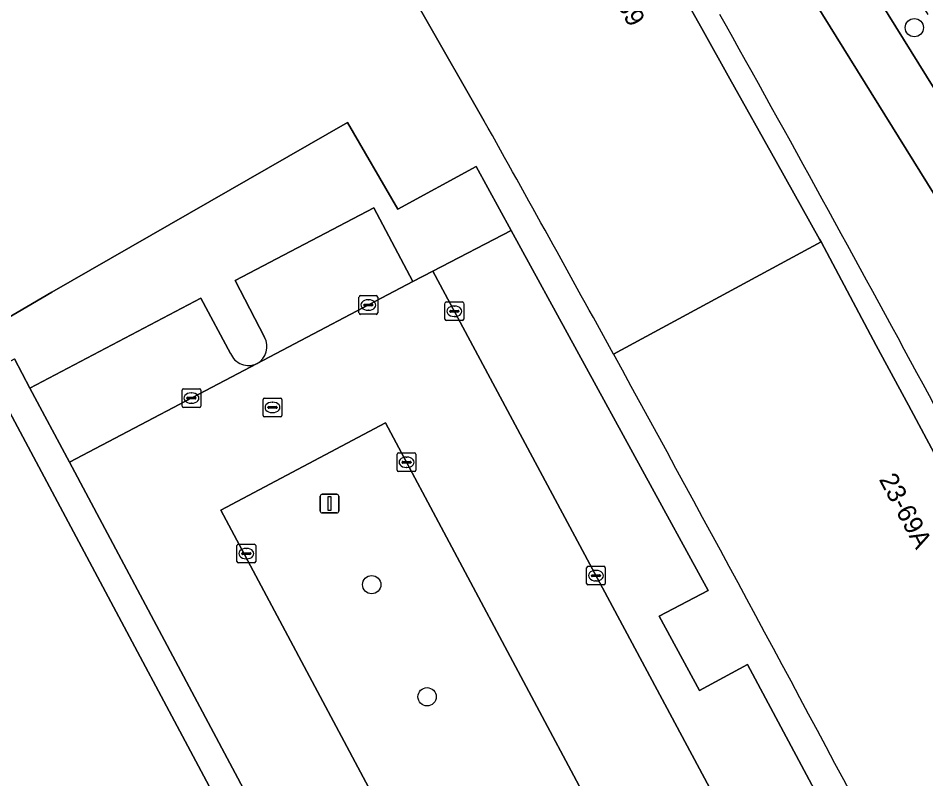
# Model space of a CAD drawing. Extents: x 160304 to 160955, y 383684 to 384161.
# Drawn here: x 160780.6 to 160829.2, y 383959.05 to 383999.81 of the extents above; entities that cross this region are included whole.
import ezdxf

# ---------------------------------------------------------------- set-up
doc = ezdxf.new("R2010")
doc.units = 0
for name, color, linetype in [('IMGEO_Boom', 7, 'Continuous'), ('IMGEO_Erf', 7, 'Continuous'), ('IMGEO_Fietspad_open', 7, 'Continuous'), ('IMGEO_Groenvoorziening', 7, 'Continuous'), ('IMGEO_Haag', 7, 'Continuous'), ('IMGEO_Kolk', 7, 'Continuous'), ('IMGEO_Lichtmast', 7, 'Continuous'), ('IMGEO_Pand', 7, 'Continuous'), ('IMGEO_Pand_nummerreeks', 7, 'Continuous'), ('IMGEO_Parkeervlak_open', 7, 'Continuous'), ('IMGEO_Rijbaan_lokaal_open', 7, 'Continuous'), ('IMGEO_Rioolput', 7, 'Continuous'), ('IMGEO_Voetpad_open', 7, 'Continuous')]:
    doc.layers.add(name, color=color, linetype=linetype)

msp = doc.modelspace()

# ---------------------------------------------------------------- linework, layer by layer
at = {"layer": 'IMGEO_Boom'}
for centre in [(160828.586, 383999.297), (160799.535, 383969.454), (160802.499, 383963.445)]:
    msp.add_circle(centre, 0.489, dxfattribs=at)
at = {"layer": 'IMGEO_Erf'}
for points in [[(160805.557, 383994.294), (160802.29, 384000), (160797.022, 384009.201)], [(160812.69, 384007.286), (160817.202, 383999.253), (160818.714, 383996.546), (160821.191, 383992.119), (160823.516, 383987.966), (160823.591, 383987.825), (160826.547, 383982.272), (160828.272, 383979.078), (160832.639, 383970.896), (160838.66, 383959.615), (160839.632, 383960.211)], [(160779.201, 383983.25), (160782.415, 383985.126), (160798.232, 383994.207), (160800.93, 383989.567), (160805.122, 383991.849), (160806.997, 383988.421), (160817.543, 383969.142), (160814.927, 383967.761), (160817.081, 383963.773), (160819.647, 383965.18), (160824.324, 383956.417), (160820.023, 383954.079), (160822.082, 383950.245), (160822.177, 383950.069), (160822.338, 383950.156), (160822.731, 383950.367), (160823.414, 383949.093), (160823.931, 383948.129), (160828.069, 383940.418), (160824.093, 383938.301)], [(160773.144, 383991.809), (160792.547, 383955.437), (160789.439, 383953.779), (160789.901, 383952.915), (160792.759, 383954.5), (160793.228, 383953.573), (160794.841, 383954.422), (160783.352, 383976.011), (160781.236, 383979.986), (160780.405, 383981.548)]]:
    msp.add_lwpolyline(points, dxfattribs=at)
for centre, radius, start, end in [((159525.369, 383277.181), 1481.154, 27.461144, 29.2099), ((159123.204, 383053.921), 1927.333, 28.779303, 29.203562), ((159143.463, 383065.194), 1904.149, 27.815062, 28.775508)]:
    msp.add_arc(centre, radius, start, end, dxfattribs=at)
at = {"layer": 'IMGEO_Fietspad_open'}
for points in [[(160751.873, 384115.337), (160755.715, 384109.34), (160755.728, 384109.32), (160788.518, 384056.578), (160823.662, 384000), (160830.017, 383989.77), (160839.554, 383974.387)], [(160842.328, 383975.591), (160832.842, 383990.888), (160827.177, 384000), (160814.975, 384019.629), (160813.456, 384022.072), (160805.259, 384035.309), (160768.526, 384094.486), (160764.835, 384100.432), (160758.942, 384109.926), (160757.079, 384112.871)]]:
    msp.add_lwpolyline(points, dxfattribs=at)
at = {"layer": 'IMGEO_Groenvoorziening'}
msp.add_lwpolyline([(160829.327, 384000), (160823.073, 384010.065), (160816.551, 384020.604), (160814.975, 384019.629), (160827.177, 384000), (160832.842, 383990.888), (160842.328, 383975.591)], dxfattribs=at)
at = {"layer": 'IMGEO_Haag'}
msp.add_lwpolyline([(160829.327, 384000), (160823.073, 384010.065), (160816.551, 384020.604), (160814.975, 384019.629), (160827.177, 384000), (160832.842, 383990.888), (160842.328, 383975.591)], dxfattribs=at)
at = {"layer": 'IMGEO_Kolk'}
for p, q in [((160798.852, 383984.011), (160798.852, 383984.863)), ((160798.927, 383984.937), (160799.779, 383984.937)), ((160799.853, 383984.863), (160799.853, 383984.011)), ((160799.111, 383984.431), (160799.111, 383984.443)), ((160799.549, 383984.394), (160799.151, 383984.394)), ((160799.154, 383984.48), (160799.552, 383984.48)), ((160799.34, 383984.717), (160799.365, 383984.717)), ((160799.595, 383984.443), (160799.595, 383984.431)), ((160803.456, 383983.674), (160803.456, 383984.526)), ((160803.531, 383984.6), (160804.383, 383984.6)), ((160803.944, 383984.38), (160803.969, 383984.38)), ((160804.457, 383984.526), (160804.457, 383983.674)), ((160799.779, 383983.937), (160798.927, 383983.937)), ((160799.363, 383984.157), (160799.338, 383984.157)), ((160803.715, 383984.094), (160803.715, 383984.106)), ((160804.153, 383984.057), (160803.755, 383984.057)), ((160803.758, 383984.143), (160804.156, 383984.143)), ((160804.199, 383984.106), (160804.199, 383984.094)), ((160804.383, 383983.6), (160803.531, 383983.6)), ((160803.967, 383983.82), (160803.942, 383983.82)), ((160789.38, 383979.024), (160789.38, 383979.876)), ((160789.455, 383979.95), (160790.307, 383979.95)), ((160789.868, 383979.73), (160789.893, 383979.73)), ((160790.381, 383979.876), (160790.381, 383979.024)), ((160789.639, 383979.444), (160789.639, 383979.456)), ((160790.077, 383979.407), (160789.679, 383979.407)), ((160789.682, 383979.493), (160790.08, 383979.493)), ((160789.891, 383979.17), (160789.866, 383979.17)), ((160790.123, 383979.456), (160790.123, 383979.444)), ((160790.307, 383978.95), (160789.455, 383978.95)), ((160800.897, 383975.584), (160800.897, 383976.436)), ((160800.972, 383976.51), (160801.824, 383976.51)), ((160801.385, 383976.29), (160801.41, 383976.29)), ((160801.898, 383976.436), (160801.898, 383975.584)), ((160801.156, 383976.004), (160801.156, 383976.016)), ((160801.594, 383975.967), (160801.196, 383975.967)), ((160801.199, 383976.053), (160801.597, 383976.053)), ((160801.408, 383975.73), (160801.383, 383975.73)), ((160801.64, 383976.016), (160801.64, 383976.004)), ((160801.824, 383975.51), (160800.972, 383975.51)), ((160792.32, 383970.69), (160792.32, 383971.542)), ((160792.395, 383971.616), (160793.247, 383971.616)), ((160792.808, 383971.396), (160792.833, 383971.396)), ((160793.321, 383971.542), (160793.321, 383970.69)), ((160792.579, 383971.11), (160792.579, 383971.122)), ((160793.017, 383971.073), (160792.619, 383971.073)), ((160792.622, 383971.159), (160793.02, 383971.159)), ((160792.831, 383970.836), (160792.806, 383970.836)), ((160793.063, 383971.122), (160793.063, 383971.11)), ((160793.247, 383970.616), (160792.395, 383970.616)), ((160811.037, 383969.51), (160811.037, 383970.362)), ((160811.112, 383970.436), (160811.964, 383970.436)), ((160812.038, 383970.362), (160812.038, 383969.51)), ((160811.296, 383969.93), (160811.296, 383969.942)), ((160811.734, 383969.893), (160811.336, 383969.893)), ((160811.339, 383969.979), (160811.737, 383969.979)), ((160811.525, 383970.216), (160811.55, 383970.216)), ((160811.78, 383969.942), (160811.78, 383969.93)), ((160811.964, 383969.436), (160811.112, 383969.436)), ((160811.548, 383969.656), (160811.523, 383969.656))]:
    msp.add_line(p, q, dxfattribs=at)
for points in [[(160798.852, 383984.011), (160798.852, 383984.863)], [(160798.927, 383984.937), (160799.779, 383984.937)], [(160799.853, 383984.863), (160799.853, 383984.011)], [(160803.456, 383983.674), (160803.456, 383984.526)], [(160803.531, 383984.6), (160804.383, 383984.6)], [(160804.457, 383984.526), (160804.457, 383983.674)], [(160799.779, 383983.937), (160798.927, 383983.937)], [(160804.383, 383983.6), (160803.531, 383983.6)], [(160789.38, 383979.024), (160789.38, 383979.876)], [(160789.455, 383979.95), (160790.307, 383979.95)], [(160790.381, 383979.876), (160790.381, 383979.024)], [(160790.307, 383978.95), (160789.455, 383978.95)], [(160800.897, 383975.584), (160800.897, 383976.436)], [(160800.972, 383976.51), (160801.824, 383976.51)], [(160801.898, 383976.436), (160801.898, 383975.584)], [(160801.824, 383975.51), (160800.972, 383975.51)], [(160792.32, 383970.69), (160792.32, 383971.542)], [(160792.395, 383971.616), (160793.247, 383971.616)], [(160793.321, 383971.542), (160793.321, 383970.69)], [(160793.247, 383970.616), (160792.395, 383970.616)], [(160811.037, 383969.51), (160811.037, 383970.362)], [(160811.112, 383970.436), (160811.964, 383970.436)], [(160812.038, 383970.362), (160812.038, 383969.51)], [(160811.964, 383969.436), (160811.112, 383969.436)]]:
    msp.add_lwpolyline(points, dxfattribs=at)
for centre, radius, start, end in [((160798.929, 383984.861), 0.0765, 91.552, 178.448), ((160798.929, 383984.861), 0.0765, 91.552, 178.448), ((160799.777, 383984.861), 0.0765, 1.552, 88.448), ((160799.777, 383984.861), 0.0765, 1.552, 88.448), ((160799.151, 383984.44), 0.0403, 85.8775, 175.7526), ((160799.148, 383984.43), 0.0366, 178.938, 274.7102), ((160799.552, 383984.437), 0.043, 264.8664, 352.4533), ((160799.556, 383984.442), 0.0386, 1.7309, 96.639), ((160803.533, 383984.524), 0.0765, 91.552, 178.448), ((160803.533, 383984.524), 0.0765, 91.552, 178.448), ((160804.381, 383984.524), 0.0765, 1.552, 88.448), ((160804.381, 383984.524), 0.0765, 1.552, 88.448), ((160798.929, 383984.013), 0.0765, 181.552, 268.448), ((160798.929, 383984.013), 0.0765, 181.552, 268.448), ((160799.777, 383984.013), 0.0765, 271.552, 358.448), ((160799.777, 383984.013), 0.0765, 271.552, 358.448), ((160803.755, 383984.103), 0.0403, 85.8775, 175.7526), ((160803.752, 383984.093), 0.0366, 178.938, 274.7102), ((160804.156, 383984.1), 0.043, 264.8664, 352.4533), ((160804.16, 383984.105), 0.0386, 1.7309, 96.639), ((160803.533, 383983.676), 0.0765, 181.552, 268.448), ((160803.533, 383983.676), 0.0765, 181.552, 268.448), ((160804.381, 383983.676), 0.0765, 271.552, 358.448), ((160804.381, 383983.676), 0.0765, 271.552, 358.448), ((160789.457, 383979.874), 0.0765, 91.552, 178.448), ((160789.457, 383979.874), 0.0765, 91.552, 178.448), ((160790.305, 383979.874), 0.0765, 1.552, 88.448), ((160790.305, 383979.874), 0.0765, 1.552, 88.448), ((160789.679, 383979.453), 0.0403, 85.8775, 175.7526), ((160789.676, 383979.443), 0.0366, 178.938, 274.7102), ((160790.08, 383979.45), 0.043, 264.8664, 352.4533), ((160790.084, 383979.455), 0.0386, 1.7309, 96.639), ((160789.457, 383979.026), 0.0765, 181.552, 268.448), ((160789.457, 383979.026), 0.0765, 181.552, 268.448), ((160790.305, 383979.026), 0.0765, 271.552, 358.448), ((160790.305, 383979.026), 0.0765, 271.552, 358.448), ((160800.974, 383976.434), 0.0765, 91.552, 178.448), ((160800.974, 383976.434), 0.0765, 91.552, 178.448), ((160801.822, 383976.434), 0.0765, 1.552, 88.448), ((160801.822, 383976.434), 0.0765, 1.552, 88.448), ((160801.196, 383976.013), 0.0403, 85.8775, 175.7526), ((160801.193, 383976.003), 0.0366, 178.938, 274.7102), ((160801.597, 383976.01), 0.043, 264.8664, 352.4533), ((160801.601, 383976.015), 0.0386, 1.7309, 96.639), ((160800.974, 383975.586), 0.0765, 181.552, 268.448), ((160800.974, 383975.586), 0.0765, 181.552, 268.448), ((160801.822, 383975.586), 0.0765, 271.552, 358.448), ((160801.822, 383975.586), 0.0765, 271.552, 358.448), ((160792.397, 383971.54), 0.0765, 91.552, 178.448), ((160792.397, 383971.54), 0.0765, 91.552, 178.448), ((160793.245, 383971.54), 0.0765, 1.552, 88.448), ((160793.245, 383971.54), 0.0765, 1.552, 88.448), ((160792.619, 383971.119), 0.0403, 85.8775, 175.7526), ((160792.616, 383971.109), 0.0366, 178.938, 274.7102), ((160793.02, 383971.116), 0.043, 264.8664, 352.4533), ((160793.024, 383971.121), 0.0386, 1.7309, 96.639), ((160792.397, 383970.692), 0.0765, 181.552, 268.448), ((160792.397, 383970.692), 0.0765, 181.552, 268.448), ((160793.245, 383970.692), 0.0765, 271.552, 358.448), ((160793.245, 383970.692), 0.0765, 271.552, 358.448), ((160811.114, 383970.36), 0.0765, 91.552, 178.448), ((160811.114, 383970.36), 0.0765, 91.552, 178.448), ((160811.962, 383970.36), 0.0765, 1.552, 88.448), ((160811.962, 383970.36), 0.0765, 1.552, 88.448), ((160811.336, 383969.939), 0.0403, 85.8775, 175.7526), ((160811.333, 383969.929), 0.0366, 178.938, 274.7102), ((160811.737, 383969.936), 0.043, 264.8664, 352.4533), ((160811.741, 383969.941), 0.0386, 1.7309, 96.639), ((160811.114, 383969.512), 0.0765, 181.552, 268.448), ((160811.114, 383969.512), 0.0765, 181.552, 268.448), ((160811.962, 383969.512), 0.0765, 271.552, 358.448), ((160811.962, 383969.512), 0.0765, 271.552, 358.448)]:
    msp.add_arc(centre, radius, start, end, dxfattribs=at)
for centre, major_axis, ratio, start_param, end_param in [((160799.339, 383984.437), (-0.387, 0.002), 0.722429, 4.712389, 7.853982), ((160799.364, 383984.437), (-0.39, 0.002), 0.717154, 1.570796, 4.712389), ((160803.943, 383984.1), (-0.387, 0.002), 0.722429, 4.712389, 7.853982), ((160803.968, 383984.1), (-0.39, 0.002), 0.717154, 1.570796, 4.712389), ((160789.867, 383979.45), (-0.387, 0.002), 0.722429, 4.712389, 7.853982), ((160789.892, 383979.45), (-0.39, 0.002), 0.717154, 1.570796, 4.712389), ((160801.384, 383976.01), (-0.387, 0.002), 0.722429, 4.712389, 7.853982), ((160801.409, 383976.01), (-0.39, 0.002), 0.717154, 1.570796, 4.712389), ((160792.807, 383971.116), (-0.387, 0.002), 0.722429, 4.712389, 7.853982), ((160792.832, 383971.116), (-0.39, 0.002), 0.717154, 1.570796, 4.712389), ((160811.524, 383969.936), (-0.387, 0.002), 0.722429, 4.712389, 7.853982), ((160811.549, 383969.936), (-0.39, 0.002), 0.717154, 1.570796, 4.712389)]:
    msp.add_ellipse(centre, major_axis=major_axis, ratio=ratio, start_param=start_param, end_param=end_param, dxfattribs=at)
at = {"layer": 'IMGEO_Lichtmast'}
for p, q in [((160796.781, 383973.394), (160796.781, 383974.194)), ((160796.781, 383974.194), (160796.781, 383973.394)), ((160796.881, 383974.294), (160797.671, 383974.294)), ((160797.671, 383974.294), (160796.881, 383974.294)), ((160797.771, 383974.194), (160797.771, 383973.394)), ((160797.771, 383973.394), (160797.771, 383974.194)), ((160797.671, 383973.294), (160796.881, 383973.294)), ((160796.881, 383973.294), (160797.671, 383973.294))]:
    msp.add_line(p, q, dxfattribs=at)
msp.add_lwpolyline([(160797.201, 383974.169), (160797.351, 383974.169), (160797.351, 383973.419), (160797.201, 383973.419), (160797.201, 383974.169)], dxfattribs=at)
for centre, start, end in [((160796.881, 383974.194), 90, 180), ((160796.881, 383974.194), 90, 180), ((160797.671, 383974.194), 0, 90), ((160797.671, 383974.194), 360, 90), ((160796.881, 383973.394), 180, 270), ((160796.881, 383973.394), 180, 270), ((160797.671, 383973.394), 270, 0), ((160797.671, 383973.394), 270, 0)]:
    msp.add_arc(centre, 0.1, start, end, dxfattribs=at)
at = {"layer": 'IMGEO_Pand'}
for points in [[(160808.064, 384015.523), (160797.022, 384009.201), (160802.29, 384000), (160805.557, 383994.294)], [(160812.474, 383981.811), (160823.591, 383987.825), (160823.516, 383987.966), (160821.191, 383992.119), (160818.714, 383996.546), (160817.202, 383999.253), (160812.69, 384007.286), (160808.064, 384015.523)], [(160826.547, 383982.272), (160823.591, 383987.825), (160812.474, 383981.811)], [(160827.604, 383953.706), (160836.537, 383958.48), (160838.66, 383959.615), (160832.639, 383970.896), (160828.272, 383979.078), (160826.547, 383982.272)]]:
    msp.add_lwpolyline(points, dxfattribs=at)
msp.add_lwpolyline([(160773.144, 383991.809), (160765.23, 383987.587), (160761.577, 383985.638), (160770.706, 383968.524), (160771.843, 383969.13), (160775.968, 383961.397), (160774.814, 383960.781), (160780.961, 383949.257), (160789.439, 383953.779), (160792.547, 383955.437)], close=True, dxfattribs=at)
for centre, radius, start, end in [((159123.204, 383053.921), 1927.333, 28.779303, 29.203562), ((159143.463, 383065.194), 1904.149, 27.815062, 28.775508)]:
    msp.add_arc(centre, radius, start, end, dxfattribs=at)
at = {"layer": 'IMGEO_Parkeervlak_open'}
for points in [[(160793.392, 383981.297), (160801.739, 383985.691), (160799.649, 383989.64), (160792.215, 383985.751), (160793.8, 383982.71)], [(160791.98, 383981.842), (160790.382, 383984.808), (160781.236, 383979.986), (160783.352, 383976.011), (160793.392, 383981.297)]]:
    msp.add_lwpolyline(points, dxfattribs=at)
for points in [[(160806.997, 383988.421), (160802.804, 383986.252), (160820.023, 383954.079), (160824.324, 383956.417), (160819.647, 383965.18), (160817.081, 383963.773), (160814.927, 383967.761), (160817.543, 383969.142)], [(160811.351, 383957.327), (160800.275, 383978.122), (160791.461, 383973.452), (160802.524, 383952.671)]]:
    msp.add_lwpolyline(points, close=True, dxfattribs=at)
for centre, radius, start, end in [((160792.88, 383982.21), 1.047, 299.2691, 28.5191), ((160792.936, 383982.218), 1.027, 201.4532, 296.3359)]:
    msp.add_arc(centre, radius, start, end, dxfattribs=at)
at = {"layer": 'IMGEO_Rijbaan_lokaal_open'}
msp.add_lwpolyline([(160823.871, 383937.679), (160818.53, 383947.772), (160816.124, 383946.481), (160815.984, 383946.742), (160815.872, 383946.682), (160814.972, 383946.198), (160813.185, 383949.602), (160812.822, 383950.285), (160820.023, 383954.079), (160802.804, 383986.252), (160801.739, 383985.691), (160793.392, 383981.297), (160783.352, 383976.011), (160794.841, 383954.422), (160796.905, 383950.454)], dxfattribs=at)
msp.add_lwpolyline([(160802.524, 383952.671), (160791.461, 383973.452), (160800.275, 383978.122), (160811.351, 383957.327)], close=True, dxfattribs=at)
at = {"layer": 'IMGEO_Rioolput'}
for p, q in [((160793.72, 383978.522), (160793.72, 383979.374)), ((160793.795, 383979.448), (160794.647, 383979.448)), ((160794.208, 383979.228), (160794.233, 383979.228)), ((160794.721, 383979.374), (160794.721, 383978.522)), ((160793.979, 383978.942), (160793.979, 383978.954)), ((160794.417, 383978.905), (160794.019, 383978.905)), ((160794.022, 383978.991), (160794.42, 383978.991)), ((160794.231, 383978.668), (160794.206, 383978.668)), ((160794.463, 383978.954), (160794.463, 383978.942)), ((160794.647, 383978.448), (160793.795, 383978.448))]:
    msp.add_line(p, q, dxfattribs=at)
for points in [[(160793.72, 383978.522), (160793.72, 383979.374)], [(160793.795, 383979.448), (160794.647, 383979.448)], [(160794.721, 383979.374), (160794.721, 383978.522)], [(160794.647, 383978.448), (160793.795, 383978.448)]]:
    msp.add_lwpolyline(points, dxfattribs=at)
for centre, radius, start, end in [((160793.797, 383979.372), 0.0765, 91.552, 178.448), ((160793.797, 383979.372), 0.0765, 91.552, 178.448), ((160794.645, 383979.372), 0.0765, 1.552, 88.448), ((160794.645, 383979.372), 0.0765, 1.552, 88.448), ((160794.019, 383978.951), 0.0403, 85.8775, 175.7526), ((160794.016, 383978.941), 0.0366, 178.938, 274.7102), ((160794.42, 383978.948), 0.043, 264.8664, 352.4533), ((160794.424, 383978.953), 0.0386, 1.7309, 96.639), ((160793.797, 383978.524), 0.0765, 181.552, 268.448), ((160793.797, 383978.524), 0.0765, 181.552, 268.448), ((160794.645, 383978.524), 0.0765, 271.552, 358.448), ((160794.645, 383978.524), 0.0765, 271.552, 358.448)]:
    msp.add_arc(centre, radius, start, end, dxfattribs=at)
for centre, major_axis, ratio, start_param, end_param in [((160794.207, 383978.948), (-0.387, 0.002), 0.722429, 4.712389, 7.853982), ((160794.232, 383978.948), (-0.39, 0.002), 0.717154, 1.570796, 4.712389)]:
    msp.add_ellipse(centre, major_axis=major_axis, ratio=ratio, start_param=start_param, end_param=end_param, dxfattribs=at)
at = {"layer": 'IMGEO_Voetpad_open'}
for points in [[(160830.017, 383989.77), (160823.662, 384000), (160788.518, 384056.578), (160755.728, 384109.32), (160755.715, 384109.34)], [(160793.8, 383982.71), (160792.215, 383985.751), (160799.649, 383989.64), (160801.739, 383985.691), (160802.804, 383986.252), (160806.997, 383988.421), (160805.122, 383991.849), (160800.93, 383989.567), (160798.232, 383994.207), (160782.415, 383985.126), (160779.201, 383983.25), (160780.126, 383981.396), (160780.405, 383981.548), (160781.236, 383979.986), (160790.382, 383984.808), (160791.98, 383981.842)]]:
    msp.add_lwpolyline(points, dxfattribs=at)
for centre, radius, start, end in [((159525.369, 383277.181), 1481.154, 27.461144, 29.2099), ((160792.88, 383982.21), 1.047, 299.2691, 28.5191), ((160792.936, 383982.218), 1.027, 201.4532, 296.3359)]:
    msp.add_arc(centre, radius, start, end, dxfattribs=at)

# ---------------------------------------------------------------- texts
at = {"layer": 'IMGEO_Pand_nummerreeks'}
for s, rotation, p in [('71-89', 299.2264, (160811.678, 384002.254)), ('23-69A', 297.9659, (160826.671, 383975.094))]:
    msp.add_text(s, height=1, rotation=rotation, dxfattribs=at).set_placement(p)

doc.saveas('drawing.dxf')
